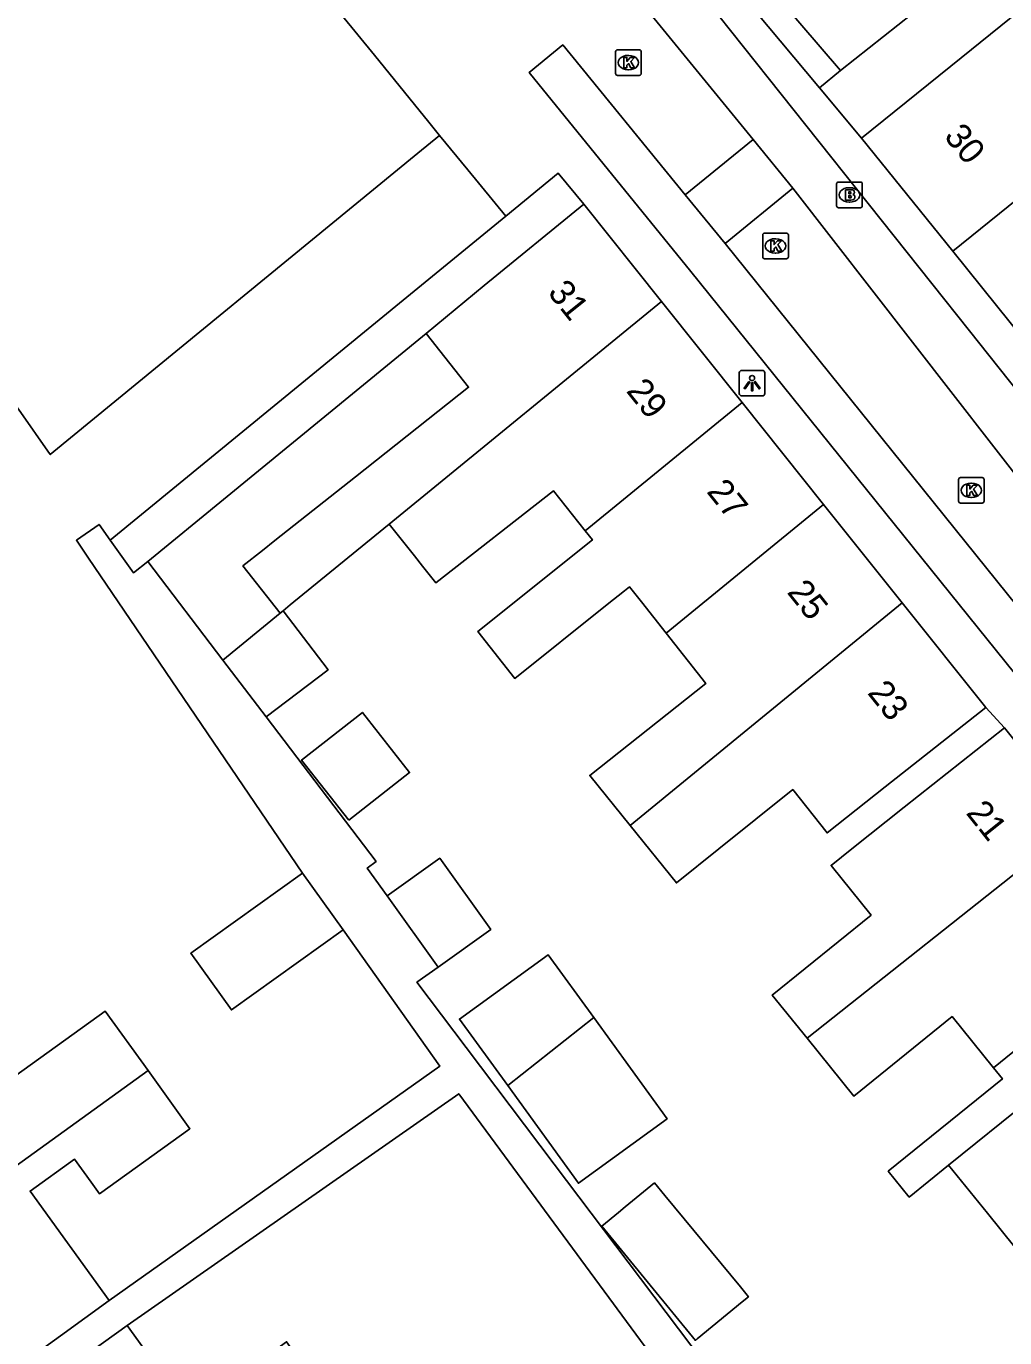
# Model space of a CAD drawing. Extents: x 161882 to 162509, y 381687 to 382379.
# Drawn here: x 162177.6 to 162215.8, y 381980.9 to 382032.1 of the extents above; entities that cross this region are included whole.
import ezdxf

# ---------------------------------------------------------------- set-up
doc = ezdxf.new("R2010")
doc.units = 0
for name, color, linetype in [('IMGEO_Brandkraan', 7, 'Continuous'), ('IMGEO_Kolk', 7, 'Continuous'), ('IMGEO_Lichtpunt', 7, 'Continuous'), ('IMGEO_Pand', 7, 'Continuous'), ('IMGEO_Pand_nummerreeks', 7, 'Continuous'), ('IMGEO_Parkeervlak_open', 7, 'Continuous'), ('IMGEO_Rijbaan_lokaal_open', 7, 'Continuous'), ('IMGEO_Voetpad_open', 7, 'Continuous')]:
    doc.layers.add(name, color=color, linetype=linetype)

msp = doc.modelspace()

# ---------------------------------------------------------------- linework, layer by layer
at = {"layer": 'IMGEO_Brandkraan'}
for p, q in [((162209.22, 382025.11), (162209.22, 382025.962)), ((162209.295, 382026.036), (162210.147, 382026.036)), ((162209.708, 382025.816), (162209.733, 382025.816)), ((162210.221, 382025.962), (162210.221, 382025.11)), ((162209.731, 382025.256), (162209.706, 382025.256)), ((162210.147, 382025.036), (162209.295, 382025.036))]:
    msp.add_line(p, q, dxfattribs=at)
for points in [[(162209.22, 382025.11), (162209.22, 382025.962)], [(162209.295, 382026.036), (162210.147, 382026.036)], [(162209.568, 382025.736), (162209.568, 382025.336), (162209.781, 382025.336)], [(162209.799, 382025.736), (162209.568, 382025.736)], [(162209.747, 382025.655), (162209.693, 382025.655), (162209.693, 382025.579)], [(162210.221, 382025.962), (162210.221, 382025.11)], [(162209.693, 382025.579), (162209.746, 382025.579)], [(162209.755, 382025.503), (162209.693, 382025.503), (162209.693, 382025.422)], [(162209.693, 382025.422), (162209.755, 382025.422)], [(162210.147, 382025.036), (162209.295, 382025.036)]]:
    msp.add_lwpolyline(points, dxfattribs=at)
for centre, radius, start, end in [((162209.297, 382025.96), 0.0765, 91.552, 178.448), ((162209.297, 382025.96), 0.0765, 91.552, 178.448), ((162209.748, 382025.617), 0.0379, 267.8285, 90.9355), ((162209.803, 382025.591), 0.145, 59.4692, 91.5367), ((162209.828, 382025.638), 0.0922, 285.5137, 58.1501), ((162210.145, 382025.96), 0.0765, 1.552, 88.448), ((162210.145, 382025.96), 0.0765, 1.552, 88.448), ((162209.297, 382025.112), 0.0765, 181.552, 268.448), ((162209.297, 382025.112), 0.0765, 181.552, 268.448), ((162209.756, 382025.462), 0.0404, 269.8759, 90.5077), ((162209.787, 382025.587), 0.251, 268.6676, 293.5347), ((162209.833, 382025.446), 0.105, 301.3115, 78.989), ((162210.145, 382025.112), 0.0765, 271.552, 358.448), ((162210.145, 382025.112), 0.0765, 271.552, 358.448)]:
    msp.add_arc(centre, radius, start, end, dxfattribs=at)
for centre, major_axis, ratio, start_param, end_param in [((162209.707, 382025.536), (-0.387, 0.002), 0.722429, 4.712389, 7.853982), ((162209.732, 382025.536), (-0.39, 0.002), 0.717154, 1.570796, 4.712389)]:
    msp.add_ellipse(centre, major_axis=major_axis, ratio=ratio, start_param=start_param, end_param=end_param, dxfattribs=at)
at = {"layer": 'IMGEO_Kolk'}
for p, q in [((162200.588, 382030.275), (162200.588, 382031.127)), ((162200.663, 382031.201), (162201.515, 382031.201)), ((162201.076, 382030.981), (162201.101, 382030.981)), ((162201.589, 382031.127), (162201.589, 382030.275)), ((162201.099, 382030.421), (162201.074, 382030.421)), ((162201.515, 382030.201), (162200.663, 382030.201)), ((162206.335, 382023.118), (162206.335, 382023.97)), ((162206.41, 382024.044), (162207.262, 382024.044)), ((162206.823, 382023.824), (162206.848, 382023.824)), ((162207.336, 382023.97), (162207.336, 382023.118)), ((162206.846, 382023.264), (162206.821, 382023.264)), ((162207.262, 382023.044), (162206.41, 382023.044)), ((162213.98, 382013.576), (162213.98, 382014.428)), ((162214.055, 382014.502), (162214.907, 382014.502)), ((162214.981, 382014.428), (162214.981, 382013.576)), ((162214.468, 382014.282), (162214.493, 382014.282)), ((162214.907, 382013.502), (162214.055, 382013.502)), ((162214.491, 382013.722), (162214.466, 382013.722))]:
    msp.add_line(p, q, dxfattribs=at)
for points in [[(162200.588, 382030.275), (162200.588, 382031.127)], [(162200.663, 382031.201), (162201.515, 382031.201)], [(162200.909, 382030.901), (162201.032, 382030.901), (162201.032, 382030.75), (162201.162, 382030.901), (162201.326, 382030.901), (162201.18, 382030.75), (162201.333, 382030.501), (162201.181, 382030.501), (162201.096, 382030.665), (162201.032, 382030.598), (162201.032, 382030.501), (162200.909, 382030.501), (162200.909, 382030.901)], [(162201.589, 382031.127), (162201.589, 382030.275)], [(162201.515, 382030.201), (162200.663, 382030.201)], [(162206.335, 382023.118), (162206.335, 382023.97)], [(162206.41, 382024.044), (162207.262, 382024.044)], [(162206.656, 382023.744), (162206.779, 382023.744), (162206.779, 382023.593), (162206.909, 382023.744), (162207.073, 382023.744), (162206.927, 382023.593), (162207.08, 382023.344), (162206.928, 382023.344), (162206.843, 382023.508), (162206.779, 382023.441), (162206.779, 382023.344), (162206.656, 382023.344), (162206.656, 382023.744)], [(162207.336, 382023.97), (162207.336, 382023.118)], [(162207.262, 382023.044), (162206.41, 382023.044)], [(162213.98, 382013.576), (162213.98, 382014.428)], [(162214.055, 382014.502), (162214.907, 382014.502)], [(162214.981, 382014.428), (162214.981, 382013.576)], [(162214.301, 382014.202), (162214.424, 382014.202), (162214.424, 382014.051), (162214.554, 382014.202), (162214.718, 382014.202), (162214.572, 382014.051), (162214.725, 382013.802), (162214.573, 382013.802), (162214.488, 382013.966), (162214.424, 382013.899), (162214.424, 382013.802), (162214.301, 382013.802), (162214.301, 382014.202)], [(162214.907, 382013.502), (162214.055, 382013.502)]]:
    msp.add_lwpolyline(points, dxfattribs=at)
for centre, start, end in [((162200.665, 382031.125), 91.552, 178.448), ((162200.665, 382031.125), 91.552, 178.448), ((162201.513, 382031.125), 1.552, 88.448), ((162201.513, 382031.125), 1.552, 88.448), ((162200.665, 382030.277), 181.552, 268.448), ((162200.665, 382030.277), 181.552, 268.448), ((162201.513, 382030.277), 271.552, 358.448), ((162201.513, 382030.277), 271.552, 358.448), ((162206.412, 382023.968), 91.552, 178.448), ((162206.412, 382023.968), 91.552, 178.448), ((162207.26, 382023.968), 1.552, 88.448), ((162207.26, 382023.968), 1.552, 88.448), ((162206.412, 382023.12), 181.552, 268.448), ((162206.412, 382023.12), 181.552, 268.448), ((162207.26, 382023.12), 271.552, 358.448), ((162207.26, 382023.12), 271.552, 358.448), ((162214.057, 382014.426), 91.552, 178.448), ((162214.057, 382014.426), 91.552, 178.448), ((162214.905, 382014.426), 1.552, 88.448), ((162214.905, 382014.426), 1.552, 88.448), ((162214.057, 382013.578), 181.552, 268.448), ((162214.057, 382013.578), 181.552, 268.448), ((162214.905, 382013.578), 271.552, 358.448), ((162214.905, 382013.578), 271.552, 358.448)]:
    msp.add_arc(centre, 0.0765, start, end, dxfattribs=at)
for centre, major_axis, ratio, start_param, end_param in [((162201.075, 382030.701), (-0.387, 0.002), 0.722429, 4.712389, 7.853982), ((162201.1, 382030.701), (-0.39, 0.002), 0.717154, 1.570796, 4.712389), ((162206.822, 382023.544), (-0.387, 0.002), 0.722429, 4.712389, 7.853982), ((162206.847, 382023.544), (-0.39, 0.002), 0.717154, 1.570796, 4.712389), ((162214.467, 382014.002), (-0.387, 0.002), 0.722429, 4.712389, 7.853982), ((162214.492, 382014.002), (-0.39, 0.002), 0.717154, 1.570796, 4.712389)]:
    msp.add_ellipse(centre, major_axis=major_axis, ratio=ratio, start_param=start_param, end_param=end_param, dxfattribs=at)
at = {"layer": 'IMGEO_Lichtpunt'}
for p, q in [((162205.421, 382018.588), (162205.421, 382017.781)), ((162205.421, 382018.588), (162205.421, 382017.781)), ((162206.323, 382018.683), (162205.515, 382018.683)), ((162206.323, 382018.683), (162205.515, 382018.683)), ((162206.417, 382017.781), (162206.417, 382018.588)), ((162206.417, 382017.781), (162206.417, 382018.588)), ((162205.515, 382017.687), (162206.323, 382017.687)), ((162205.515, 382017.687), (162206.323, 382017.687))]:
    msp.add_line(p, q, dxfattribs=at)
for points in [[(162205.795, 382018.252), (162205.834, 382018.224), (162205.646, 382017.962), (162205.608, 382017.989), (162205.795, 382018.252)], [(162205.897, 382018.204), (162205.944, 382018.204), (162205.944, 382017.882), (162205.897, 382017.882), (162205.897, 382018.204)], [(162206.007, 382018.224), (162206.045, 382018.251), (162206.232, 382017.989), (162206.193, 382017.961), (162206.007, 382018.224)]]:
    msp.add_lwpolyline(points, dxfattribs=at)
msp.add_circle((162205.92, 382018.386), 0.0994, dxfattribs=at)
for centre, start, end in [((162205.515, 382018.588), 90, 180), ((162205.515, 382018.588), 90, 180), ((162206.323, 382018.588), 0, 90), ((162206.323, 382018.588), 0, 90), ((162205.515, 382017.781), 180, 270), ((162205.515, 382017.781), 180, 270), ((162206.323, 382017.781), 270, 0), ((162206.323, 382017.781), 270, 360)]:
    msp.add_arc(centre, 0.0946, start, end, dxfattribs=at)
at = {"layer": 'IMGEO_Pand'}
for points in [[(162152.462, 382018.996), (162166.618, 382030.597), (162166.459, 382030.79), (162181.344, 382042.988), (162191.177, 382030.989), (162192.732, 382029.062), (162193.295, 382028.375), (162193.718, 382027.859)], [(162233.036, 382038.902), (162229.038, 382042.959), (162214.086, 382030.889), (162210.195, 382027.748)], [(162209.375, 382030.397), (162205.408, 382035.023)], [(162215.442, 382035.2), (162213.296, 382033.501), (162209.375, 382030.397)], [(162213.756, 382023.338), (162224.622, 382032.11)], [(162193.718, 382027.859), (162192.868, 382027.162), (162178.511, 382015.397), (162177.271, 382017.167), (162176.155, 382018.528), (162176.553, 382018.855), (162171.139, 382025.462), (162160.651, 382016.868), (162156.783, 382013.698), (162156.187, 382014.426)], [(162210.195, 382027.748), (162213.756, 382023.338)], [(162199.346, 382025.168), (162195.462, 382021.995), (162193.193, 382020.121)], [(162199.346, 382025.168), (162202.381, 382021.371)], [(162217.176, 382019.101), (162213.756, 382023.338)], [(162191.752, 382012.687), (162202.381, 382021.371)], [(162202.381, 382021.371), (162205.531, 382017.428)], [(162193.193, 382020.121), (162194.85, 382018.028), (162190.433, 382014.533), (162187.288, 382012.044), (162186.799, 382011.657), (162186.034, 382011.052), (162187.494, 382009.207)], [(162199.405, 382012.42), (162205.531, 382017.428)], [(162205.531, 382017.428), (162208.713, 382013.446)], [(162199.405, 382012.42), (162198.164, 382013.988), (162193.566, 382010.395), (162193.054, 382011.042), (162192.731, 382011.451), (162191.752, 382012.687)], [(162208.713, 382013.446), (162202.568, 382008.424)], [(162208.713, 382013.446), (162211.783, 382009.604)], [(162191.752, 382012.687), (162188.732, 382010.219), (162187.887, 382009.528), (162187.606, 382009.299)], [(162202.568, 382008.424), (162201.601, 382009.645), (162201.286, 382010.042), (162201.129, 382010.241), (162200.933, 382010.084), (162200.262, 382009.547), (162196.652, 382006.662), (162195.209, 382008.485), (162199.687, 382012.064), (162199.405, 382012.42)], [(162187.606, 382009.299), (162189.361, 382006.996), (162186.943, 382005.155)], [(162187.494, 382009.207), (162187.606, 382009.299)], [(162201.156, 382000.919), (162211.783, 382009.604)], [(162211.783, 382009.604), (162215.043, 382005.525)], [(162187.494, 382009.207), (162185.252, 382007.375)], [(162201.156, 382000.919), (162199.58, 382002.874), (162204.117, 382006.466), (162202.568, 382008.424)], [(162186.943, 382005.155), (162185.252, 382007.375)], [(162190.167, 382001.122), (162192.542, 382002.982), (162190.701, 382005.333), (162188.326, 382003.474), (162190.167, 382001.122)], [(162215.043, 382005.525), (162211.123, 382002.423), (162208.851, 382000.625), (162207.511, 382002.319), (162204.618, 382000), (162202.965, 381998.675), (162201.156, 382000.919)], [(162208.068, 381992.613), (162206.704, 381994.3), (162210.568, 381997.423), (162209.003, 381999.357), (162209.811, 382000), (162211.858, 382001.63), (162215.779, 382004.732)], [(162215.779, 382004.732), (162218.725, 382001.041)], [(162208.068, 381992.613), (162217.408, 382000), (162218.725, 382001.041)], [(162191.672, 381998.17), (162193.722, 381999.639), (162195.713, 381996.861), (162193.662, 381995.392)], [(162189.949, 381996.843), (162185.586, 381993.717), (162183.998, 381995.933), (162188.36, 381999.06)], [(162188.36, 381999.06), (162189.949, 381996.843)], [(162193.662, 381995.392), (162191.672, 381998.17)], [(162222.052, 381996.872), (162218.164, 381993.729), (162215.349, 381991.453)], [(162196.376, 381990.761), (162194.49, 381993.36), (162197.951, 381995.873), (162199.735, 381993.417)], [(162213.594, 381987.654), (162216.723, 381990.185), (162219.278, 381992.251), (162223.166, 381995.394)], [(162173.415, 381992.621), (162175.186, 381993.898), (162177.164, 381991.155), (162180.657, 381993.673), (162182.33, 381991.35)], [(162199.735, 381993.417), (162202.603, 381989.466), (162199.141, 381986.953), (162196.376, 381990.761)], [(162199.735, 381993.417), (162196.376, 381990.761)], [(162215.349, 381991.453), (162213.727, 381993.459), (162209.891, 381990.357), (162208.068, 381992.613)], [(162182.33, 381991.35), (162170.985, 381983.17)], [(162182.33, 381991.35), (162183.968, 381989.079), (162180.436, 381986.533), (162180.106, 381986.991), (162179.455, 381987.894), (162177.724, 381986.645), (162180.808, 381982.369)], [(162216.713, 381983.795), (162215.108, 381985.78), (162214.602, 381986.407), (162213.594, 381987.654)], [(162202.513, 381986.47), (162205.464, 381982.902), (162205.777, 381982.52), (162205.538, 381982.323), (162203.775, 381980.876), (162203.704, 381980.817), (162200.046, 381985.27), (162200.705, 381985.811), (162200.969, 381986.028), (162202.108, 381986.963), (162202.513, 381986.47)], [(162180.808, 381982.369), (162178.91, 381980.999), (162174.716, 381977.972)], [(162175.413, 381977.002), (162179.573, 381979.999), (162181.521, 381981.402)], [(162181.521, 381981.402), (162184.595, 381977.135), (162186.287, 381978.354), (162185.642, 381979.251), (162187.741, 381980.763), (162189.059, 381978.933)]]:
    msp.add_lwpolyline(points, dxfattribs=at)
at = {"layer": 'IMGEO_Parkeervlak_open'}
for points in [[(162205.956, 382027.701), (162207.512, 382025.796)], [(162204.863, 382023.632), (162203.307, 382025.537)]]:
    msp.add_lwpolyline(points, dxfattribs=at)
at = {"layer": 'IMGEO_Rijbaan_lokaal_open'}
for points in [[(162190.279, 382051.904), (162200.94, 382038.82), (162208.554, 382029.711)], [(162205.956, 382027.701), (162197.948, 382037.505), (162199.568, 382038.828), (162201.169, 382036.868), (162214.404, 382020.232), (162227.861, 382003.318), (162240.04, 381988.01)], [(162234.651, 381983.483), (162216.168, 382006.86), (162203.528, 382022.543), (162197.21, 382030.314), (162198.527, 382031.389), (162203.307, 382025.537)], [(162208.554, 382029.711), (162210.195, 382027.748)], [(162196.3, 382024.708), (162194.817, 382026.518), (162193.718, 382027.859)], [(162203.307, 382025.537), (162205.956, 382027.701)], [(162196.3, 382024.708), (162198.347, 382026.389), (162199.346, 382025.168)], [(162207.512, 382025.796), (162204.863, 382023.632)], [(162238.73, 381986.904), (162226.199, 382001.747), (162207.512, 382025.796)], [(162204.863, 382023.632), (162217.503, 382007.949), (162235.986, 381984.572)], [(162215.779, 382004.732), (162215.043, 382005.525)]]:
    msp.add_lwpolyline(points, dxfattribs=at)
at = {"layer": 'IMGEO_Voetpad_open'}
for points in [[(162209.375, 382030.397), (162208.554, 382029.711)], [(162180.856, 382012.052), (162192.433, 382021.539), (162196.3, 382024.708)], [(162182.32, 382011.225), (162185.282, 382013.648), (162193.193, 382020.121)], [(162188.36, 381999.06), (162180.006, 382011.355), (162179.532, 382012.052), (162180.42, 382012.674), (162180.856, 382012.052)], [(162182.32, 382011.225), (162181.77, 382010.775), (162180.856, 382012.052)], [(162185.252, 382007.375), (162182.32, 382011.225)], [(162186.943, 382005.155), (162191.236, 381999.518), (162190.893, 381999.257), (162191.672, 381998.17)], [(162180.808, 381982.369), (162193.721, 381991.52), (162189.949, 381996.843)], [(162193.662, 381995.392), (162192.829, 381994.795), (162194.751, 381992.25), (162198.189, 381987.697), (162205.454, 381978.078)], [(162213.594, 381987.654), (162212.056, 381986.412), (162211.24, 381987.422), (162215.695, 381991.025), (162215.349, 381991.453)], [(162181.521, 381981.402), (162194.462, 381990.444), (162203.852, 381977.701), (162205.677, 381975.269)]]:
    msp.add_lwpolyline(points, dxfattribs=at)

# ---------------------------------------------------------------- texts
at = {"layer": 'IMGEO_Pand_nummerreeks'}
for s, rotation, p in [('30', 308.9151, (162213.384, 382027.808)), ('31', 308.6286, (162197.908, 382021.713)), ('29', 308.6286, (162200.977, 382017.873)), ('27', 308.6286, (162204.116, 382013.944)), ('25', 308.6286, (162207.255, 382010.016)), ('23', 308.6286, (162210.395, 382006.087)), ('21', 308.5963, (162214.243, 382001.398))]:
    msp.add_text(s, height=1, rotation=rotation, dxfattribs=at).set_placement(p)

doc.saveas('drawing.dxf')
